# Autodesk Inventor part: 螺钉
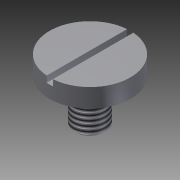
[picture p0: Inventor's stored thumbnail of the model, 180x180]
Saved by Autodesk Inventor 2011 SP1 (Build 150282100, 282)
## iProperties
Created: 2013-11
Part Number: 螺钉
Document SubType Name: Modeling
Designer: Administrator
Density: 1 g/cm^3
Author: Administrator
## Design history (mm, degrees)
sketch "草图1"
  geometry: C1 r 13 at (0, 0); 1 further point
  constraints: 1 centre point, 1 coincident
  dimensions: "d0" = 26 diameter of C1
extrude "拉伸1" new body sketch "草图1" distance "d1" = 6; taper "d2" = 0 deg
sketch "草图2"
  geometry: L1 (-1, -13)-(1, -13); L2 (1, -13)-(1, 13); L3 (1, 13)-(-1, 13); L4 (-1, 13)-(-1, -13); C1 r 13 at (0, 0) reference; 2 further points
  constraints: 8 end point, 2 midpoint, 2 parallel, 1 horizontal, 1 horizontal alignment, 1 perpendicular, 1 vertical alignment
  dimensions: "d3" = 2 distance of L1.start L1.end; "d4" = 26 distance of L3.end L1.start
extrude "拉伸2" cut sketch "草图2" distance "d5" = 2; taper "d6" = 0 deg
sketch "草图4"
  geometry: C1 r 13 at (0, 0) reference; C2 r 5 at (0, 0)
  constraints: 1 centre point, 1 coincident
  dimensions: "d13" = 10 diameter of C2
extrude "拉伸4" join sketch "草图4" distance "d14" = 1; taper "d15" = 0 deg
sketch "草图5"
  geometry: C1 r 5 at (0, 0) reference
extrude "拉伸5" join sketch "草图5" distance "d16" = 13; taper "d17" = 0 deg
feature "螺纹1" dims "d18" = 10, "d19" = 0
chamfer "倒角2" distance "d20" = 1; stored, may be unused: second distance "d21" = 2, angle "d22" = 45 deg
node "实体1"
